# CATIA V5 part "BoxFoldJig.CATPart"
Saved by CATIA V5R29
Part number: BoxFoldJig
Source: Unknown
Bounding box of the stored display mesh (mm): x -128.606 to 128.606, y -217.253 to 131.984, z 141.34 to 260
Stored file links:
  C:\가치같이\SmartFactory_BoxErectorConveyor\Boxing(under)\BoxFoldJig.CATPart
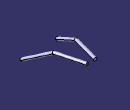
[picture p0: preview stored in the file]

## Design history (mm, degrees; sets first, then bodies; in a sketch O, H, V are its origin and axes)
Body1 "PartBody.1" (main body)
  Solid1: solid without history
Body2 "PartBody.2"
  Solid2: solid without history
